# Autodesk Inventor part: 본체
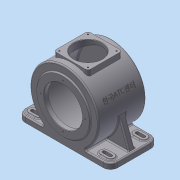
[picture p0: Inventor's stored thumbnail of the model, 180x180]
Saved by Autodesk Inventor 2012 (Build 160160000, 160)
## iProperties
Created: 2015-06
Part Number: 본체
Material: 알루미늄-6061
Document SubType Name: Modeling
Designer: Administrator
Density: 2.71 g/cm^3
Mass: 3293.83 g
Surface Area: 2306.13 cm^2
Volume: 1215.43 cm^3
Author: Administrator
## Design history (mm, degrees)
sketch "스케치1"
  geometry: C1 r 85 at (0, 0); 1 further point
  constraints: 1 centre point, 1 coincident
  dimensions: "d0" = 170 diameter of C1
extrude "돌출1" new body sketch "스케치1" stored distance "d1" = 118; taper "d2" = 0 deg
feature "쉘1" dims "d4" = 8
node "작업 평면11"
sketch "스케치3"
  geometry: C1 r 65 at (0, 0); 1 further point
  constraints: 1 centre point, 1 coincident
  dimensions: "d8" = 130 diameter of C1
sketch "스케치4"
  geometry: C1 r 31 at (0, 0); 1 further point
  constraints: 1 centre point, 1 coincident
  dimensions: "d20" = 62 diameter of C1
extrude "돌출4" join sketch "스케치4" distance "d21" = 3.5; taper "d22" = 0 deg
feature "면 기울기1" dims angle "d41" = 25 deg
node "작업 평면2"
  node "작업 평면1"
sketch "스케치5"
  geometry: L1 (-35.5, 42.5)-(35.5, 42.5); L2 (42.5, 35.5)-(42.5, -35.5); L3 (35.5, -42.5)-(-35.5, -42.5); L4 (-42.5, -35.5)-(-42.5, 35.5); L5 (-42.5, -42.5)-(42.5, 42.5); A1 r 7 centre (-35.5, 35.5) between (-35.5, 42.5) and (-42.5, 35.5); A2 r 7 centre (35.5, 35.5) between (42.5, 35.5) and (35.5, 42.5); A3 r 7 centre (35.5, -35.5) between (35.5, -42.5) and (42.5, -35.5); A4 r 7 centre (-35.5, -35.5) between (-42.5, -35.5) and (-35.5, -42.5); 4 further points
  constraints: 10 end point, 8 point on circle, 8 point on line, 8 tangent, 4 centre point, 3 equal radius, 2 parallel, 1 coincident, 1 horizontal, 1 midpoint, 1 perpendicular
  dimensions: "d44" = 85 distance of point (42.5, -42.5) L5.start; "d45" = 85 distance of L5.start point (-42.5, 42.5); "d46" = 7 radius of A1
extrude "돌출5" join sketch "스케치5" stored distance "d47" = 3.5; taper "d48" = 0 deg
sketch "스케치6"
  geometry: C1 r 35 at (0, 0); 1 further point
  constraints: 1 centre point, 1 coincident
  dimensions: "d49" = 70 diameter of C1
extrude "돌출6" cut sketch "스케치6" stored distance "d50" = 3.5; taper "d51" = 0 deg
sketch "스케치7"
  geometry: A1 r 7 centre (-35.5, 35.5) between (-35.5, 42.5) and (-42.5, 35.5) reference; A2 r 7 centre (-35.5, -35.5) between (-42.5, -35.5) and (-35.5, -42.5) reference; A3 r 7 centre (35.5, -35.5) between (35.5, -42.5) and (42.5, -35.5) reference; A4 r 7 centre (35.5, 35.5) between (42.5, 35.5) and (35.5, 42.5) reference; 5 further points
  constraints: 4 coincident
  dimensions: "d52" = 71 distance of point (35.5, 35.5) point (-35.5, 35.5) (derived); "d53" = 71 distance of point (-35.5, -35.5) point (-35.5, 35.5) (derived)
hole "구멍4" sketch "스케치7" at (-35.5, 35.5), (35.5, 35.5), (35.5, -35.5), (-35.5, -35.5) diameter "d54" = 3.242; stored, may be unused: countersink angle "d58" = 90 deg, drill point angle "d60" = 118 deg; dims "d55" = 10, "d56" = 4, "d57" = 2, "d59" = 13
node "작업 평면9"
node "작업 평면3"
node "작업 평면12"
sketch "스케치11"
  geometry: L1 (-59, -71)-(59, -71); L2 (59, -71)-(59, -85); L3 (59, -85)-(-59, -85); L4 (-59, -85)-(-59, -71); 2 further points
  constraints: 8 end point, 2 parallel, 1 horizontal, 1 midpoint, 1 perpendicular
  dimensions: "d83" = 14 distance of L1.end L2.end; "d84" = 118 distance of L2.end L3.end; "d98" = 85 distance from line of L3 point (0, 0)
extrude "돌출9" join sketch "스케치11" stored distance "d86" = 10; taper "d87" = 0 deg
sketch "스케치13"
  geometry: C1 r 65 at (0, 0); 1 further point
  constraints: 1 centre point, 1 coincident
  dimensions: "d101" = 130 diameter of C1
extrude "돌출13" join sketch "스케치13" distance "d102" = 3; taper "d103" = 0 deg
sketch "스케치8"
  geometry: 5 further points
  dimensions: "d63" = 110 distance of point (0, 55) point (0, -55); "d64" = 110 distance of point (55, 0) point (-55, 0); "d104" = 55 distance of point (0, 0) point (55, 0); "d105" = 55 distance of point (0, 55) point (0, 0)
hole "구멍5" sketch "스케치8" at (0, 55), (-55, 0), (55, 0), (0, -55) diameter "d65" = 3.242; stored, may be unused: countersink angle "d69" = 90 deg, drill point angle "d71" = 118 deg; dims "d66" = 10, "d67" = 4, "d68" = 2, "d70" = 11
extrude "돌출11" join sketch "스케치3" distance "d90" = 13; taper "d91" = 0 deg
node "작업 평면13"
sketch "스케치12"
  geometry: L1 (59, -71)-(-59, -71); L2 (-59, -71)-(-59, -85); L3 (-59, -85)-(59, -85); L4 (59, -85)-(59, -71); 2 further points
  constraints: 8 end point, 2 parallel, 1 horizontal, 1 midpoint, 1 perpendicular, 1 vertical alignment
  dimensions: "d93" = 118 distance of L2.end L3.end; "d94" = 14 distance of L3.end L1.start; "d95" = 85 distance from line of L3 point (0, 0)
extrude "돌출12" join sketch "스케치12" stored distance "d96" = 13; taper "d97" = 0 deg
fillet "모깎기2" dims "d107" = 18
sketch "스케치14"
  geometry: L1 (-34, 9)-(-18, 9); L2 (-18, 27)-(-34, 27); A1 r 9 centre (-18, 18) between (-18, 9) and (-18, 27); A2 r 9 centre (-34, 18) between (-34, 27) and (-34, 9); A3 r 18 centre (-18, 18) between (-18, 0) and (0, 18) reference; 1 further point
  constraints: 4 end point, 4 point on circle, 4 tangent, 2 centre point, 1 coincident, 1 horizontal, 1 parallel
  dimensions: "d108" = 18 distance between parallel lines of L1 L2; "d109" = 16 distance of A2.centre A1.centre
extrude "돌출14" join sketch "스케치14" distance "d110" = 3; taper "d111" = 0 deg
sketch "스케치15"
  geometry: L1 (-34, 27)-(-18, 27) reference; L2 (-18, 9)-(-34, 9) reference; L3 (-18, 14)-(-34, 14); L4 (-34, 22)-(-18, 22); A1 r 9 centre (-18, 18) between (-18, 9) and (-18, 27) reference; A2 r 9 centre (-34, 18) between (-34, 27) and (-34, 9) reference; A3 r 4 centre (-18, 18) between (-18, 14) and (-18, 22); A4 r 4 centre (-34, 18) between (-34, 22) and (-34, 14); 1 further point
  constraints: 4 end point, 4 point on circle, 2 centre point, 3 other
  dimensions: "d112" = 24 dimension on A3 A4
extrude "돌출15" cut sketch "스케치15" stored distance "d113" = 3; taper "d114" = 0 deg
fillet "모깎기6" dims "d142" = 3
sketch "스케치16"
  geometry: L1 (-109, -71)-(-84.87, -4.703); L2 (-115, -74)-(-115, -85) reference; L3 (-106, -71)-(-97, -71) reference; A1 r 85 centre (0, 0) between (46.733, -71) and (-46.733, -71) reference; 1 further point
  constraints: 2 end point, 1 point on circle
  dimensions: "d140" = 6 distance from line of L1.start L2; "d148" = 110 deg angle of L3 L1
feature "리브1" sketch "스케치16" dims "d121" = 1, "d122" = 15, "d123" = 0, "d124" = 0, "d125" = 1, "d126" = 1
fillet "모깎기4" dims "d131" = 3
sketch "스케치19"
  geometry: C1 r 47.5 at (0, 0); 1 further point
  constraints: 1 centre point, 1 coincident
  dimensions: "d143" = 95 diameter of C1
extrude "돌출17" cut sketch "스케치19" distance "d144" = 11; taper "d145" = 0 deg
node "작업 평면16"
node "작업 평면17"
sketch "스케치18"
  geometry: L1 (-41, 7)-(41, 7); L2 (41, 7)-(41, -7); L3 (41, -7)-(-41, -7); L4 (-41, -7)-(-41, 7); L5 (-41, -7)-(41, 7); 2 further points
  constraints: 2 end point, 1 coincident, 1 midpoint, 1 vertical, 2 other
  dimensions: "d135" = 82 distance of L2.end L3.end; "d136" = 14 distance of L3.end L1.start
feature "엠보싱1" sketch "스케치18" dims "d137" = 0.5, "d138" = 0
fillet "모깎기7" dims "d146" = 3
chamfer "모따기1" distance "d149" = 1; stored, may be unused: second distance "d150" = 2, angle "d151" = 45 deg
fillet "모깎기8" dims "d152" = 3
fillet "모깎기10" dims "d154" = 3
hole "구멍6" diameter "d162" = 47; stored, may be unused: countersink angle "d166" = 90 deg, drill point angle "d168" = 0 deg; dims "d160" = 10, "d161" = 10, "d163" = 6, "d164" = 4, "d165" = 2, "d167" = 14
hole "구멍7" diameter "d171" = 30; stored, may be unused: countersink angle "d175" = 90 deg, drill point angle "d177" = 0 deg; dims "d169" = 10, "d170" = 10, "d172" = 6, "d173" = 4, "d174" = 2, "d176" = 3
chamfer "모따기2" distance "d178" = 1; stored, may be unused: second distance "d179" = 2, angle "d180" = 45 deg
fillet "모깎기12" dims "d181" = 3, "d182" = 0.3
node "솔리드1"
pattern_linear "직사각형 패턴1" dims "d117" = 82, "d120" = 178
mirror "대칭1"
other parameters: "d42" = 3, "d92" = -115, "d134" = 65 deg
